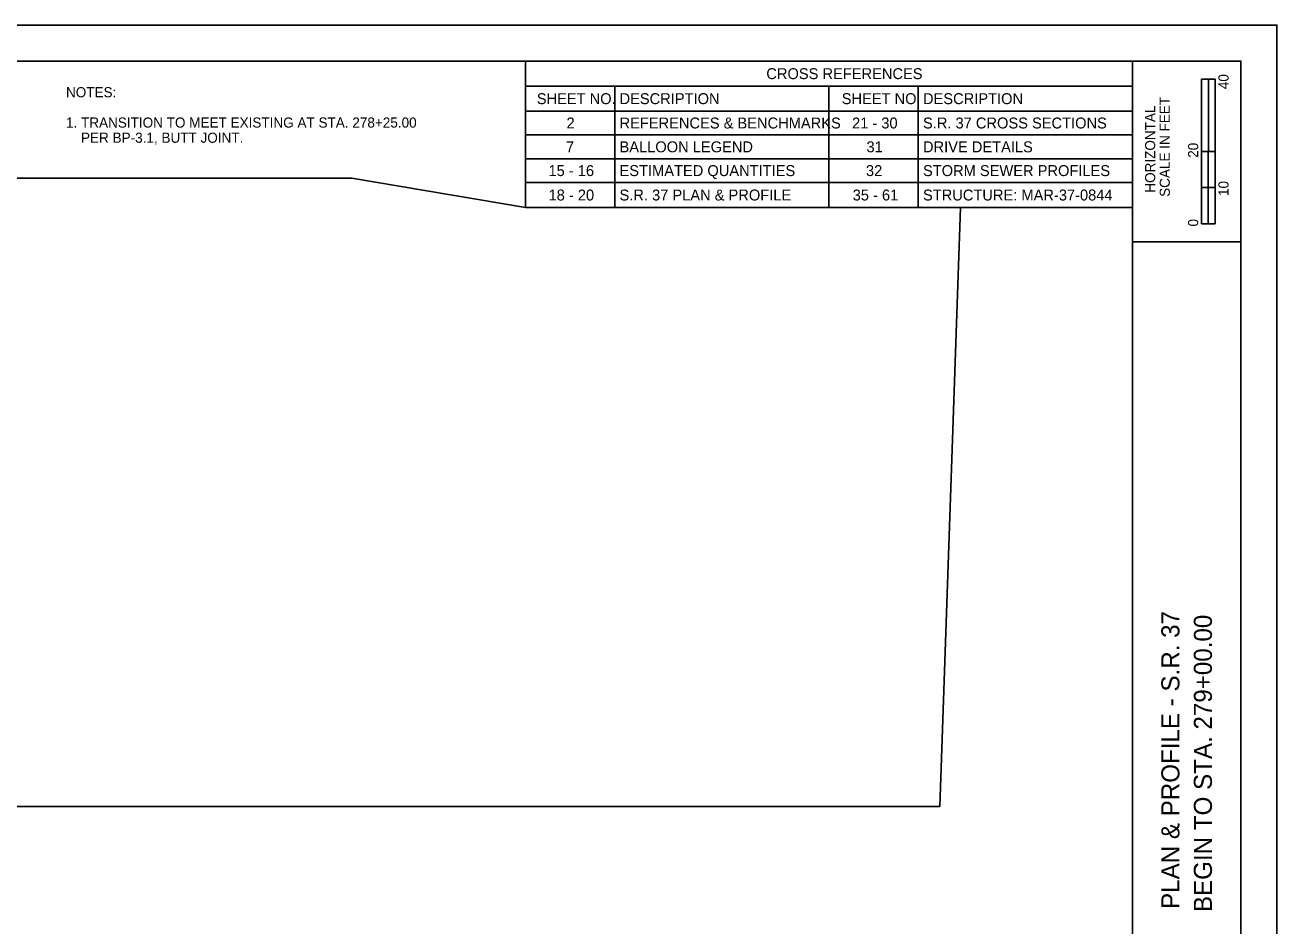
# Model space of a CAD drawing. Extents: x -0.7 to 34, y 0 to 22.
# Drawn here: x 16.67 to 34, y 9.53 to 22 of the extents above; entities that cross this region are included whole.
import ezdxf

# ---------------------------------------------------------------- set-up
doc = ezdxf.new("R2010")
doc.units = 0
for name, color, linetype in [('RW_X_CL', 7, 'Continuous'), ('RW_X_CL_100_Bearings', 7, 'Continuous'), ('RW_X_Esmt_SH', 7, 'Continuous'), ('RW_X_Fee_RW', 7, 'Continuous'), ('SC_Scratch1', 7, 'Continuous')]:
    doc.layers.add(name, color=color, linetype=linetype)

msp = doc.modelspace()

# ---------------------------------------------------------------- linework, layer by layer
at = {"layer": 'RW_X_CL'}
for p, q in [((23.6, 21.5), (32, 21.5)), ((32, 21.5), (32, 19.474)), ((32.957, 19.25), (32.957, 21.25)), ((33.144, 21.25), (32.957, 21.25)), ((32.957, 20.25), (32.957, 21.25)), ((32.957, 21.25), (33.05, 21.25)), ((33.05, 21.25), (33.051, 21.25)), ((33.051, 21.25), (33.051, 20.25)), ((33.144, 21.25), (33.144, 19.25)), ((33.051, 20.25), (32.957, 20.25)), ((33.143, 20.25), (33.05, 20.25)), ((33.05, 20.25), (33.05, 19.75)), ((33.143, 19.75), (33.143, 20.25)), ((33.05, 19.75), (32.957, 19.75)), ((32.957, 19.75), (32.957, 19.25)), ((33.05, 19.25), (33.05, 19.75)), ((33.05, 19.75), (33.143, 19.75)), ((33.144, 19.25), (32.957, 19.25)), ((32.957, 19.25), (33.05, 19.25))]:
    msp.add_line(p, q, dxfattribs=at)
at = {"layer": 'RW_X_CL_100_Bearings'}
for p, q in [((23.6, 21.5), (32, 21.5)), ((23.6, 21.5), (23.6, 19.474)), ((32, 21.5), (32, 19.474)), ((23.6, 21.154), (32, 21.154)), ((24.835, 21.154), (24.835, 19.474)), ((27.8, 21.154), (27.8, 19.474)), ((29.035, 21.154), (29.035, 19.474)), ((23.6, 20.808), (32, 20.808)), ((23.6, 20.479), (32, 20.479)), ((23.6, 20.149), (32, 20.149)), ((23.6, 19.82), (32, 19.82)), ((23.6, 19.474), (32, 19.474))]:
    msp.add_line(p, q, dxfattribs=at)
at = {"layer": 'RW_X_Esmt_SH'}
msp.add_lwpolyline([(0, 0), (34, 0), (34, 22), (0, 22)], close=True, dxfattribs=at)
at = {"layer": 'RW_X_Fee_RW'}
msp.add_lwpolyline([(4.25, 19.88), (21.195, 19.88), (23.6, 19.474), (29.621, 19.474), (29.332, 11.184), (15.305, 11.183), (15.305, 12.189), (4.25, 12.189)], close=True, dxfattribs=at)
at = {"layer": 'SC_Scratch1'}
for p, q in [((32, 0.5), (32, 21.5)), ((32, 19), (33.5, 19))]:
    msp.add_line(p, q, dxfattribs=at)
msp.add_lwpolyline([(1.5, 21.5), (33.5, 21.5), (33.5, 0.5), (1.5, 0.5)], close=True, dxfattribs=at)

# ---------------------------------------------------------------- texts
at = {"layer": 'RW_X_CL'}
for s, height, p in [('40', 0.14, (33.33, 21.112)), ('SCALE IN FEET', 0.14, (32.517, 19.621)), ('HORIZONTAL', 0.14, (32.315, 19.679)), ('20', 0.14, (32.91, 20.162)), ('10', 0.14, (33.33, 19.633)), ('0', 0.14, (32.91, 19.211)), ('PLAN & PROFILE - S.R. 37', 0.25, (32.65, 9.764)), ('BEGIN TO STA. 279+00.00', 0.25, (33.1, 9.721))]:
    msp.add_text(s, height=height, rotation=90, dxfattribs=at).set_placement(p)
at = {"layer": 'RW_X_CL_100_Bearings'}
for s, height, p in [('CROSS REFERENCES', 0.15153, (26.933, 21.251)), ('NOTES:', 0.14, (17.24, 21)), ('SHEET NO.', 0.1515, (23.756, 20.905)), ('DESCRIPTION', 0.15153, (24.901, 20.905)), ('SHEET NO', 0.1515, (27.976, 20.905)), ('DESCRIPTION', 0.15153, (29.101, 20.905)), ('1. TRANSITION TO MEET EXISTING AT STA. 278+25.00', 0.14, (17.24, 20.58)), ('2', 0.152, (24.167, 20.568)), ('REFERENCES & BENCHMARKS', 0.15153, (24.901, 20.568)), ('21 - 30', 0.1515, (28.119, 20.568)), ('S.R. 37 CROSS SECTIONS', 0.15153, (29.101, 20.568)), ('    PER BP-3.1, BUTT JOINT.', 0.14, (17.24, 20.37)), ('7', 0.152, (24.16, 20.238)), ('BALLOON LEGEND', 0.15153, (24.901, 20.238)), ('31', 0.1515, (28.319, 20.238)), ('DRIVE DETAILS', 0.15153, (29.101, 20.238)), ('15 - 16', 0.1515, (23.918, 19.909)), ('ESTIMATED QUANTITIES', 0.15153, (24.901, 19.909)), ('32', 0.1515, (28.312, 19.909)), ('STORM SEWER PROFILES', 0.15153, (29.101, 19.909)), ('18 - 20', 0.1515, (23.919, 19.571)), ('S.R. 37 PLAN & PROFILE', 0.15153, (24.901, 19.571)), ('35 - 61', 0.1515, (28.128, 19.571)), ('STRUCTURE: MAR-37-0844', 0.15153, (29.101, 19.571))]:
    msp.add_text(s, height=height, dxfattribs=at).set_placement(p)

doc.saveas('drawing.dxf')
